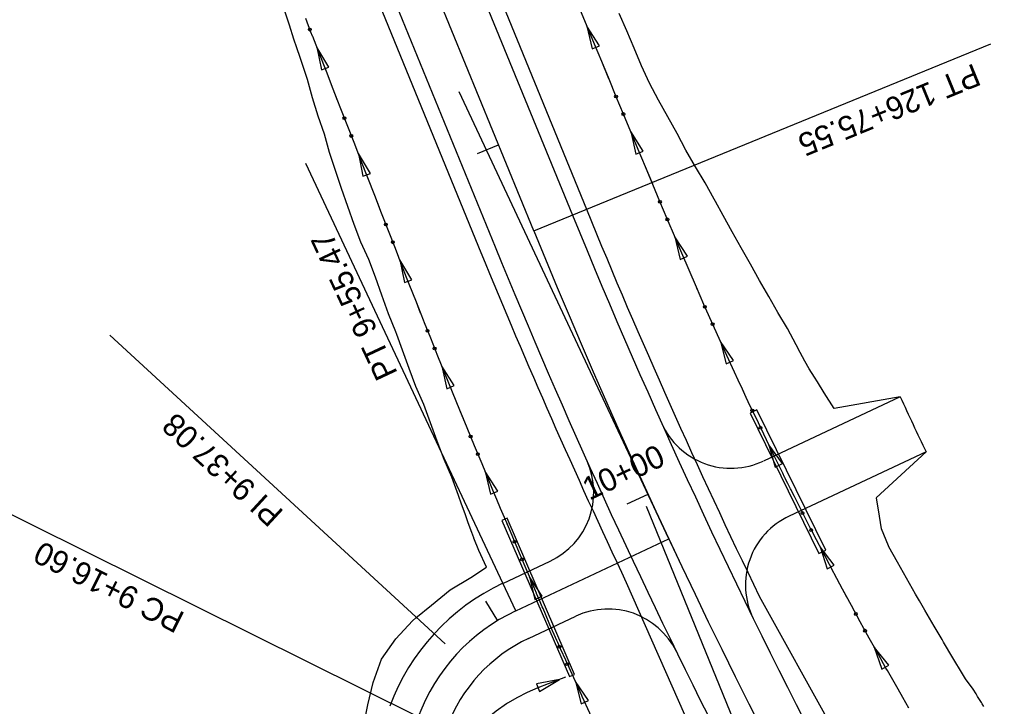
# Model space of a CAD drawing. Extents: x 916431 to 921570, y 1763982 to 1768032.
# Drawn here: x 918429.9 to 918689.4, y 1765705.9 to 1765886.5 of the extents above; entities that cross this region are included whole.
import ezdxf

# ---------------------------------------------------------------- set-up
doc = ezdxf.new("R2010")
doc.units = 0
for name, color, linetype in [('R_Drainage', 7, 'Continuous'), ('R_Horz Alg', 7, 'Continuous'), ('R_Horz Alg Annot', 7, 'Continuous'), ('R_Horz Alg Stationing', 7, 'Continuous'), ('R_Proposed Const Limits', 7, 'Continuous'), ('R_Proposed Road', 7, 'Continuous'), ('R_Shld', 7, 'Continuous'), ('R_Special Ditch', 7, 'Continuous')]:
    doc.layers.add(name, color=color, linetype=linetype)

msp = doc.modelspace()

# ---------------------------------------------------------------- linework, layer by layer
at = {"layer": 'R_Drainage'}
for p, q in [((918623.99, 1765783.88), (918622.19, 1765783)), ((918642.11, 1765746.97), (918623.99, 1765783.88)), ((918622.19, 1765783), (918640.31, 1765746.09)), ((918558.23, 1765755.35), (918556.85, 1765754.75)), ((918576.01, 1765714.25), (918558.23, 1765755.35)), ((918556.85, 1765754.75), (918574.63, 1765713.65)), ((918640.31, 1765746.09), (918642.11, 1765746.97)), ((918574.63, 1765713.65), (918576.01, 1765714.25))]:
    msp.add_line(p, q, dxfattribs=at)
at = {"layer": 'R_Horz Alg'}
for p, q in [((918565.23, 1765830.96), (918442.38, 1766131.25)), ((918560.49, 1765730.97), (918600.8, 1765749.88))]:
    msp.add_line(p, q, dxfattribs=at)
for centre, radius, start, end in [((920196.91, 1766498.5), 1762.95, 202.25028, 218.97694), ((918581.72, 1765685.7), 50, 115.128, 159.6685)]:
    msp.add_arc(centre, radius, start, end, dxfattribs=at)
at = {"layer": 'R_Horz Alg Annot'}
msp.add_line((918663.37, 1765591.08), (918594.92, 1765758.39), dxfattribs=at)
for points in [[(918565.23, 1765830.96), (918685.55, 1765880.18)], [(918600.8, 1765749.88), (918545.6, 1765867.58)], [(918560.49, 1765730.97), (918505.29, 1765848.67)], [(918541.95, 1765722.28), (918453.62, 1765803.5)], [(918534.84, 1765703.08), (918418.4, 1765760.9)]]:
    msp.add_lwpolyline(points, dxfattribs=at)
at = {"layer": 'R_Horz Alg Stationing'}
for points in [[(918550.42, 1765851.32), (918555.97, 1765853.59)], [(918589.87, 1765759.16), (918595.33, 1765761.67)], [(918597.41, 1765757.12), (918604.2, 1765742.64)], [(918552.55, 1765733.5), (918555.67, 1765728.38)]]:
    msp.add_lwpolyline(points, dxfattribs=at)
at = {"layer": 'R_Proposed Const Limits'}
for p, q in [((918661.7, 1765787.28), (918644.36, 1765784.23)), ((918668.5, 1765772.79), (918655.41, 1765760.71))]:
    msp.add_line(p, q, dxfattribs=at)
for points in [[(918552.79, 1765742.46), (918550.75, 1765746.81), (918549.45, 1765750.14), (918549.45, 1765750.15), (918548.92, 1765751.62), (918548.02, 1765754.1), (918547.17, 1765756.46), (918546.23, 1765759.05), (918545.43, 1765761.3), (918543.64, 1765766.12), (918541.65, 1765770.84), (918539.86, 1765775.65), (918538.07, 1765780.47), (918536.27, 1765785.28), (918534.21, 1765789.97), (918532.42, 1765794.78), (918530.67, 1765799.6), (918529.18, 1765803.71), (918528.93, 1765804.43), (918526.99, 1765809.17), (918525.27, 1765814), (918523.6, 1765818.74), (918521.82, 1765823.41), (918519.77, 1765827.97), (918518.01, 1765832.66), (918516.34, 1765837.38), (918514.68, 1765842.1), (918513.09, 1765846.85), (918511.51, 1765851.61), (918510.13, 1765856.44), (918508.54, 1765861.19), (918507, 1765865.97), (918505.67, 1765870.83), (918504.07, 1765875.57), (918502.49, 1765880.22), (918502.46, 1765880.32), (918502.11, 1765881.42), (918500.99, 1765885.12), (918499.38, 1765889.86)], [(918644.36, 1765784.23), (918641.73, 1765788.36), (918639.91, 1765791.23), (918639.91, 1765791.24), (918639.12, 1765792.5), (918637.78, 1765794.63), (918636.56, 1765796.67), (918635.36, 1765798.98), (918634.32, 1765800.98), (918632, 1765805.26), (918629.53, 1765809.48), (918627.08, 1765813.7), (918624.65, 1765817.94), (918622.29, 1765822.22), (918619.88, 1765826.48), (918617.49, 1765830.74), (918615.11, 1765835.02), (918613.11, 1765838.68), (918612.75, 1765839.31), (918610.36, 1765843.58), (918607.86, 1765847.82), (918605.31, 1765852.16), (918603, 1765856.62), (918600.52, 1765861.01), (918598.04, 1765865.4), (918595.74, 1765869.86), (918593.63, 1765874.4), (918591.69, 1765879.01), (918589.75, 1765883.61), (918587.74, 1765888.2)], [(918683.74, 1765705.77), (918683.29, 1765706.47), (918683.06, 1765706.84), (918682.08, 1765708.44), (918681.67, 1765709.14), (918680.92, 1765710.4), (918678.9, 1765713.05), (918678.09, 1765714.39), (918675.6, 1765718.57), (918673.13, 1765722.75), (918672.73, 1765723.43), (918670.66, 1765726.94), (918668.2, 1765731.13), (918666.76, 1765733.62), (918665.77, 1765735.34), (918663.35, 1765739.56), (918660.96, 1765743.79), (918658.75, 1765747.81), (918658.75, 1765747.82), (918658.73, 1765747.84), (918658.62, 1765748.05), (918656.77, 1765752.54), (918655.96, 1765757.54), (918655.46, 1765760.59), (918655.41, 1765760.71)], [(918514.09, 1765677.06), (918515.41, 1765681.9), (918516.85, 1765686.7), (918518.22, 1765691.52), (918519.47, 1765696.39), (918520.6, 1765701.31), (918521.6, 1765706.27), (918523.01, 1765712.12), (918525.2, 1765718.28), (918528.95, 1765723.6), (918533.35, 1765728.36), (918534.22, 1765729.16), (918538.32, 1765732.48), (918543.28, 1765736.48), (918548.72, 1765739.77), (918552.79, 1765742.46)]]:
    msp.add_lwpolyline(points, dxfattribs=at)
at = {"layer": 'R_Proposed Road'}
for p, q in [((918509.35, 1765996.59), (918575.41, 1765835.12)), ((918488.99, 1765988.25), (918555.05, 1765826.79)), ((918661.7, 1765787.28), (918625.68, 1765770.38)), ((918668.5, 1765772.79), (918632.47, 1765755.9)), ((918557.09, 1765738.21), (918569.54, 1765744.05)), ((918563.89, 1765723.73), (918576.33, 1765729.57))]:
    msp.add_line(p, q, dxfattribs=at)
for centre, radius, start, end in [((920196.91, 1766498.5), 1751.95, 202.25028, 207.5444), ((920196.91, 1766498.5), 1773.95, 202.25028, 206.91983), ((920196.91, 1766498.5), 1691.95, 204.85714, 205.39896), ((918617.18, 1765788.49), 20, 204.2017, 295.128), ((918561.04, 1765762.16), 20, 295.128, 24.2337), ((918640.96, 1765737.79), 20, 115.128, 206.0544), ((918581.72, 1765685.7), 58, 115.128, 159.6685), ((918584.82, 1765711.46), 20, 26.0224, 115.128), ((918581.72, 1765685.7), 42, 115.128, 159.6685)]:
    msp.add_arc(centre, radius, start, end, dxfattribs=at)
at = {"layer": 'R_Shld'}
for p, q in [((918513.06, 1765998.1), (918579.11, 1765836.64)), ((918485.29, 1765986.74), (918551.35, 1765825.28)), ((918589.61, 1765738.44), (918609.83, 1765692.64)), ((918624.6, 1765734.85), (918648.86, 1765691.11))]:
    msp.add_line(p, q, dxfattribs=at)
for radius, end in [(1747.95, 205.90546), (1777.95, 205.30854)]:
    msp.add_arc((920196.91, 1766498.5), radius, 202.25028, end, dxfattribs=at)
at = {"layer": 'R_Special Ditch'}
for p, q in [((918579.25, 1765884.83), (918580.58, 1765878.88)), ((918582.54, 1765879.7), (918579.25, 1765884.83)), ((918508.16, 1765879.28), (918509.35, 1765873.3)), ((918511.33, 1765874.07), (918508.16, 1765879.28)), ((918580.58, 1765878.88), (918582.54, 1765879.7)), ((918509.35, 1765873.3), (918511.33, 1765874.07)), ((918590.79, 1765857.1), (918592.12, 1765851.15)), ((918594.08, 1765851.97), (918590.79, 1765857.1)), ((918592.12, 1765851.15), (918594.08, 1765851.97)), ((918519.08, 1765851.29), (918520.27, 1765845.32)), ((918522.24, 1765846.09), (918519.08, 1765851.29)), ((918520.27, 1765845.32), (918522.24, 1765846.09)), ((918602.39, 1765829.39), (918603.76, 1765823.45)), ((918605.71, 1765824.28), (918602.39, 1765829.39)), ((918530, 1765823.31), (918531.19, 1765817.34)), ((918533.16, 1765818.11), (918530, 1765823.31)), ((918603.76, 1765823.45), (918605.71, 1765824.28)), ((918531.19, 1765817.34), (918533.16, 1765818.11)), ((918614.4, 1765801.86), (918615.92, 1765795.96)), ((918617.84, 1765796.83), (918614.4, 1765801.86)), ((918541.06, 1765795.39), (918542.35, 1765789.43)), ((918544.31, 1765790.23), (918541.06, 1765795.39)), ((918615.92, 1765795.96), (918617.84, 1765796.83)), ((918542.35, 1765789.43), (918544.31, 1765790.23)), ((918627.14, 1765774.65), (918628.81, 1765768.8)), ((918630.71, 1765769.72), (918627.14, 1765774.65)), ((918628.81, 1765768.8), (918630.71, 1765769.72)), ((918552.49, 1765767.61), (918553.82, 1765761.66)), ((918555.77, 1765762.48), (918552.49, 1765767.61)), ((918553.82, 1765761.66), (918555.77, 1765762.48)), ((918640.62, 1765747.81), (918642.48, 1765742.01)), ((918644.36, 1765743), (918640.62, 1765747.81)), ((918642.48, 1765742.01), (918644.36, 1765743)), ((918564.13, 1765739.91), (918565.5, 1765733.98)), ((918567.45, 1765734.81), (918564.13, 1765739.91)), ((918565.5, 1765733.98), (918567.45, 1765734.81)), ((918654.89, 1765721.38), (918656.91, 1765715.63)), ((918658.75, 1765716.67), (918654.89, 1765721.38)), ((918656.91, 1765715.63), (918658.75, 1765716.67)), ((918571.98, 1765712.92), (918566, 1765711.72)), ((918566, 1765711.72), (918566.78, 1765709.75)), ((918566.78, 1765709.75), (918571.98, 1765712.92)), ((918576.19, 1765712.41), (918577.72, 1765706.51)), ((918579.64, 1765707.39), (918576.19, 1765712.41)), ((918577.72, 1765706.51), (918579.64, 1765707.39))]:
    msp.add_line(p, q, dxfattribs=at)
for points in [[(918664.01, 1765705.35), (918663.22, 1765706.72), (918660.78, 1765710.97), (918658.35, 1765715.23), (918657.96, 1765715.92), (918655.95, 1765719.5), (918653.56, 1765723.78), (918652.16, 1765726.32), (918651.2, 1765728.07), (918648.85, 1765732.38), (918646.52, 1765736.69), (918644.33, 1765740.78), (918644.33, 1765740.78), (918644.32, 1765740.81), (918644.21, 1765741.01), (918641.92, 1765745.35), (918639.65, 1765749.69), (918638.26, 1765752.36), (918638.2, 1765752.48), (918637.39, 1765754.05), (918637.15, 1765754.53), (918635.17, 1765758.42), (918633.86, 1765761.03), (918633.18, 1765762.39), (918632.97, 1765762.8), (918632.83, 1765763.09), (918632.14, 1765764.47), (918632.09, 1765764.56), (918632.08, 1765764.58), (918632.07, 1765764.61), (918631.34, 1765766.08), (918631.29, 1765766.19), (918630.79, 1765767.19), (918630.52, 1765767.73), (918628.98, 1765770.86), (918628.63, 1765771.59), (918626.48, 1765776), (918624.36, 1765780.42), (918622.89, 1765783.5), (918622.89, 1765783.51), (918622.25, 1765784.85), (918621.18, 1765787.13), (918620.17, 1765789.29), (918619.06, 1765791.68), (918618.11, 1765793.74), (918616.06, 1765798.2), (918614.03, 1765802.66), (918612.03, 1765807.14), (918610.04, 1765811.62), (918608.08, 1765816.12), (918606.13, 1765820.62), (918604.2, 1765825.13), (918602.28, 1765829.64), (918600.66, 1765833.49), (918600.38, 1765834.16), (918598.47, 1765838.68), (918596.58, 1765843.2), (918594.66, 1765847.81), (918592.74, 1765852.42), (918590.82, 1765857.04), (918588.9, 1765861.66), (918586.98, 1765866.27), (918585.06, 1765870.89), (918583.13, 1765875.51), (918581.21, 1765880.12), (918579.29, 1765884.74), (918577.37, 1765889.36)], [(918580.03, 1765704.02), (918578.01, 1765708.41), (918578.01, 1765708.41), (918578, 1765708.44), (918577.9, 1765708.66), (918575.77, 1765713.31), (918573.65, 1765717.96), (918572.36, 1765720.81), (918572.3, 1765720.94), (918571.54, 1765722.61), (918571.31, 1765723.13), (918569.51, 1765727.31), (918568.31, 1765730.1), (918567.69, 1765731.56), (918567.5, 1765732), (918566.74, 1765733.79), (918566.7, 1765733.88), (918566.69, 1765733.91), (918566.67, 1765733.94), (918566, 1765735.51), (918565.95, 1765735.63), (918565.49, 1765736.7), (918565.25, 1765737.28), (918563.83, 1765740.62), (918563.5, 1765741.4), (918561.5, 1765746.11), (918559.52, 1765750.81), (918558.14, 1765754.09), (918558.13, 1765754.1), (918557.54, 1765755.52), (918556.52, 1765757.94), (918555.56, 1765760.23), (918554.51, 1765762.76), (918553.6, 1765764.94), (918551.64, 1765769.66), (918549.68, 1765774.37), (918547.74, 1765779.09), (918545.8, 1765783.81), (918543.86, 1765788.54), (918541.93, 1765793.26), (918540.01, 1765797.99), (918538.11, 1765802.72), (918536.5, 1765806.76), (918536.22, 1765807.46), (918534.34, 1765812.2), (918532.48, 1765816.95), (918530.65, 1765821.62), (918528.84, 1765826.28), (918527.02, 1765830.94), (918525.2, 1765835.6), (918523.38, 1765840.26), (918521.57, 1765844.92), (918519.75, 1765849.57), (918517.93, 1765854.23), (918516.11, 1765858.89), (918514.3, 1765863.55), (918512.48, 1765868.21), (918510.66, 1765872.87), (918508.84, 1765877.53), (918507.06, 1765882.09), (918507.03, 1765882.19), (918506.61, 1765883.26), (918505.22, 1765886.85)], [(918585.02, 1765870.98), (918583.13, 1765875.51), (918581.21, 1765880.12), (918579.29, 1765884.74), (918579.25, 1765884.83)], [(918513.61, 1765865.3), (918512.48, 1765868.21), (918510.66, 1765872.87), (918508.84, 1765877.53), (918508.16, 1765879.28)], [(918585.03, 1765870.95), (918585.02, 1765870.98)], [(918513.63, 1765865.27), (918513.61, 1765865.3)], [(918596.56, 1765843.25), (918594.66, 1765847.81), (918592.74, 1765852.42), (918590.82, 1765857.04), (918590.79, 1765857.1)], [(918524.53, 1765837.32), (918523.38, 1765840.26), (918521.57, 1765844.92), (918519.75, 1765849.57), (918519.08, 1765851.29)], [(918596.57, 1765843.21), (918596.56, 1765843.25)], [(918524.54, 1765837.28), (918524.53, 1765837.32)], [(918608.3, 1765815.6), (918608.08, 1765816.12), (918606.13, 1765820.62), (918604.2, 1765825.13), (918602.39, 1765829.39)], [(918535.47, 1765809.35), (918534.34, 1765812.2), (918532.48, 1765816.95), (918530.65, 1765821.62), (918530, 1765823.31)], [(918608.32, 1765815.57), (918608.3, 1765815.6)], [(918535.49, 1765809.31), (918535.47, 1765809.35)], [(918620.67, 1765788.23), (918620.17, 1765789.29), (918619.06, 1765791.68), (918618.11, 1765793.74), (918616.06, 1765798.2), (918614.4, 1765801.86)], [(918546.74, 1765781.5), (918545.8, 1765783.81), (918543.86, 1765788.54), (918541.93, 1765793.26), (918541.07, 1765795.39)], [(918620.68, 1765788.19), (918620.67, 1765788.23)], [(918546.76, 1765781.47), (918546.74, 1765781.5)], [(918633.77, 1765761.2), (918633.18, 1765762.39), (918632.97, 1765762.8), (918632.83, 1765763.09), (918632.14, 1765764.47), (918632.09, 1765764.56), (918632.08, 1765764.58), (918632.07, 1765764.61), (918631.34, 1765766.08), (918631.29, 1765766.19), (918630.79, 1765767.19), (918630.52, 1765767.73), (918628.98, 1765770.86), (918628.63, 1765771.59), (918627.14, 1765774.65)], [(918558.27, 1765753.77), (918558.14, 1765754.09), (918558.13, 1765754.1), (918557.54, 1765755.52), (918556.52, 1765757.94), (918555.56, 1765760.23), (918554.51, 1765762.76), (918553.6, 1765764.94), (918552.49, 1765767.61)], [(918633.79, 1765761.17), (918633.77, 1765761.2)], [(918558.29, 1765753.73), (918558.27, 1765753.77)], [(918647.66, 1765734.57), (918646.52, 1765736.69), (918644.33, 1765740.78), (918644.33, 1765740.78), (918644.32, 1765740.81), (918644.21, 1765741.01), (918641.92, 1765745.35), (918640.63, 1765747.82)], [(918570.02, 1765726.12), (918569.51, 1765727.31), (918568.31, 1765730.1), (918567.69, 1765731.56), (918567.5, 1765732), (918566.74, 1765733.79), (918566.7, 1765733.88), (918566.69, 1765733.91), (918566.67, 1765733.94), (918566, 1765735.51), (918565.95, 1765735.63), (918565.49, 1765736.7), (918565.25, 1765737.28), (918564.13, 1765739.91)], [(918647.68, 1765734.54), (918647.66, 1765734.57)], [(918570.04, 1765726.09), (918570.02, 1765726.12)], [(918662.29, 1765708.33), (918660.78, 1765710.97), (918658.35, 1765715.23), (918657.96, 1765715.92), (918655.95, 1765719.5), (918654.9, 1765721.39)], [(918528.43, 1765655.75), (918531.9, 1765665.13), (918533.85, 1765669.74), (918535.9, 1765674.31), (918538.06, 1765678.84), (918540.32, 1765683.34), (918542.68, 1765687.79), (918545.14, 1765692.21), (918547.71, 1765696.6), (918550.09, 1765699.93), (918552.63, 1765702.47), (918555.33, 1765704.65), (918558.08, 1765706.56), (918558.58, 1765706.87), (918560.85, 1765708.2), (918563.62, 1765709.61), (918566.39, 1765710.81), (918569.17, 1765711.82), (918573.65, 1765713.58)], [(918558.35, 1765706.73), (918558.58, 1765706.87), (918560.85, 1765708.2), (918563.62, 1765709.61), (918566.39, 1765710.81), (918569.17, 1765711.82), (918571.98, 1765712.92)], [(918582.5, 1765698.8), (918582.17, 1765699.38), (918580.03, 1765704.02), (918578.01, 1765708.41), (918578.01, 1765708.41), (918578, 1765708.44), (918577.9, 1765708.66), (918576.19, 1765712.41)], [(918558.32, 1765706.71), (918558.35, 1765706.73)], [(918662.31, 1765708.3), (918662.29, 1765708.33)]]:
    msp.add_lwpolyline(points, dxfattribs=at)
for centre in [(918506.31, 1765883.93), (918586.91, 1765866.33), (918588.84, 1765861.71), (918515.4, 1765860.61), (918517.22, 1765855.94), (918598.46, 1765838.6), (918600.41, 1765833.99), (918526.32, 1765832.63), (918528.14, 1765827.96), (918610.28, 1765810.99), (918537.29, 1765804.67), (918612.32, 1765806.41), (918539.16, 1765800.02), (918622.77, 1765783.67), (918624.93, 1765779.15), (918548.62, 1765776.85), (918550.54, 1765772.22), (918636, 1765756.7), (918638.28, 1765752.24), (918560.19, 1765749.12), (918562.14, 1765744.51), (918650.03, 1765730.14), (918652.44, 1765725.75), (918572, 1765721.51), (918574.08, 1765716.95)]:
    msp.add_circle(centre, 0.375, dxfattribs=at)

# ---------------------------------------------------------------- texts
at = {"layer": 'R_Horz Alg Annot'}
for s, rotation, p in [('PT 126+75.55', 202.2503, (918681.13, 1765875.13)), ('PT 9+55.47', 115.128, (918529.51, 1765793.5)), ('PI 9+37.08', 137.3983, (918499.69, 1765757.06)), ('PC 9+16.60', 153.1621, (918473.73, 1765730.27))]:
    msp.add_text(s, height=6, rotation=rotation, dxfattribs=at).set_placement(p)
at = {"layer": 'R_Horz Alg Stationing'}
msp.add_text('10+00', height=6, rotation=25.128, dxfattribs=at).set_placement((918579.9, 1765759.96))
msp.add_text('10+00', height=6, rotation=25.128, dxfattribs=at).set_placement((918579.9, 1765759.96))

doc.saveas('drawing.dxf')
